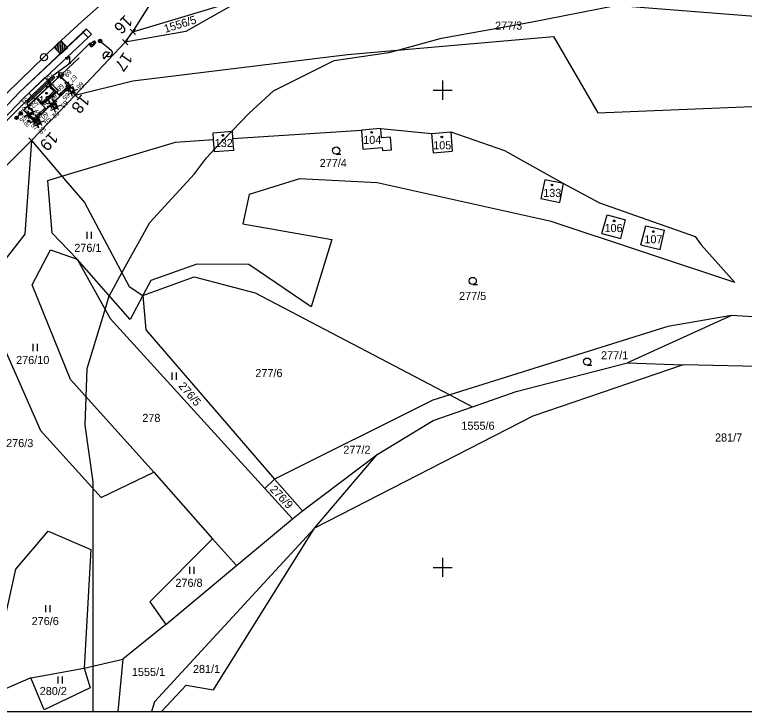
# Model space of a CAD drawing. Extents: x -756640 to -756220, y -1116031 to -1115741.
# Drawn here: x -756489.7 to -756336.8, y -1116030.2 to -1115884.2 of the extents above; entities that cross this region are included whole.
import ezdxf

# ---------------------------------------------------------------- set-up
doc = ezdxf.new("R2010")
doc.units = 0
for name, color, linetype in [('BPEJ', 7, 'Continuous'), ('GD_Demolice', 7, 'Continuous'), ('GD_Nový stav', 7, 'Continuous'), ('GD_Starý stav', 7, 'Continuous'), ('Groma (60)', 7, 'Continuous'), ('Katastr_HRANICE DRÁHY', 7, 'Continuous'), ('Katastr_Hranice parcel', 7, 'Continuous'), ('Katastr_Parcelní čísla', 7, 'Continuous'), ('Katastr_Slučkované čáry', 7, 'Continuous'), ('Katastr_Značky kultur', 7, 'Continuous'), ('Vrstva 7', 7, 'Continuous'), ('čtvercová síť', 7, 'Continuous')]:
    doc.layers.add(name, color=color, linetype=linetype)

# ---------------------------------------------------------------- blocks, each defined once
blk = doc.blocks.new('POINT_DISPLAY')
for p, q in [((-0.56, -0.56), (0.56, 0.56)), ((-0.56, 0.56), (0.56, -0.56))]:
    blk.add_line(p, q)
blk = doc.blocks.new('C691')
at = {"layer": 'čtvercová síť'}
for p, q in [((0, 0.5), (0, -0.5)), ((-0.5, 0), (0.5, 0))]:
    blk.add_line(p, q, dxfattribs=at)

msp = doc.modelspace()

# ---------------------------------------------------------------- linework, layer by layer
at = {"layer": 'BPEJ'}
msp.add_lwpolyline([(-756473.24, -1116030.18), (-756473.24, -1116029.59), (-756473.24, -1116022.8), (-756473.24, -1116020.66), (-756473.24, -1116000), (-756473.24, -1115987.16), (-756473.24, -1115983.5), (-756473.24, -1115982.06), (-756474.94, -1115970.18), (-756474.73, -1115964.28), (-756474.51, -1115958.3), (-756470.74, -1115945.96), (-756469.86, -1115943.07), (-756469.84, -1115943.03), (-756467.21, -1115938.28), (-756461.36, -1115927.75), (-756456.69, -1115922.66), (-756452.02, -1115917.57), (-756449.48, -1115914.17), (-756447.85, -1115912.47), (-756444.19, -1115908.63), (-756440.57, -1115904.84), (-756435.47, -1115900.17), (-756422.74, -1115893.8), (-756411.29, -1115892.11), (-756409.41, -1115891.6), (-756400.26, -1115889.14), (-756381.59, -1115885.74), (-756363.76, -1115882.25)], dxfattribs=at)
at = {"layer": 'Defpoints'}
msp.add_line((-756640.13, -1116030.18), (-756220.13, -1116030.18), dxfattribs=at)
at = {"layer": 'GD_Demolice'}
for p, q in [((-756471.89, -1115889.36), (-756471.83, -1115890.08)), ((-756471.61, -1115889.36), (-756471.55, -1115890.02)), ((-756471.47, -1115889.95), (-756469.46, -1115891.64)), ((-756469.79, -1115892.04), (-756471.05, -1115893.54)), ((-756478.56, -1115899.7), (-756478.39, -1115899.86)), ((-756477.8, -1115900.42), (-756478.56, -1115899.7)), ((-756478.39, -1115899.86), (-756477.91, -1115899.35)), ((-756477.32, -1115899.91), (-756478.05, -1115899.21)), ((-756477.32, -1115899.91), (-756477.91, -1115899.35)), ((-756477.8, -1115900.42), (-756477.32, -1115899.91)), ((-756481.35, -1115903.79), (-756482.11, -1115903.06)), ((-756481.94, -1115903.23), (-756481.46, -1115902.72)), ((-756481.35, -1115903.79), (-756481.94, -1115903.23)), ((-756481.6, -1115902.58), (-756480.87, -1115903.28)), ((-756481.35, -1115903.79), (-756480.87, -1115903.28)), ((-756486.67, -1115904.98), (-756486.52, -1115905.14)), ((-756485.82, -1115904.47), (-756486.52, -1115905.14)), ((-756484.86, -1115907.19), (-756485.62, -1115906.38)), ((-756484.99, -1115906.03), (-756485.47, -1115906.54)), ((-756484.86, -1115907.19), (-756485.47, -1115906.54)), ((-756485.11, -1115905.9), (-756484.38, -1115906.68)), ((-756484.86, -1115907.19), (-756484.38, -1115906.68))]:
    msp.add_line(p, q, dxfattribs=at)
for points in [[(-756482.33, -1115898.93), (-756480.22, -1115897.04), (-756478.24, -1115898.95)], [(-756486.96, -1115903.31), (-756482.33, -1115898.93), (-756480.41, -1115901)], [(-756480.41, -1115901), (-756478.24, -1115898.95), (-756478.02, -1115899.18), (-756485.7, -1115906.45), (-756486.91, -1115905.2), (-756486.67, -1115904.98)], [(-756482.33, -1115898.93), (-756480.41, -1115901), (-756478.24, -1115898.95)], [(-756486.96, -1115903.31), (-756485.82, -1115904.47)]]:
    msp.add_lwpolyline(points, dxfattribs=at)
msp.add_circle((-756471.76, -1115889.71), 0.375, dxfattribs=at)
msp.add_circle((-756471.76, -1115889.71), 0.375, dxfattribs=at)
for centre, start, end in [((-756470.43, -1115892.78), 49.3451, 230.7502), ((-756469.94, -1115892.21), 230.0476, 50.0476)]:
    msp.add_arc(centre, 0.75, start, end, dxfattribs=at)
at = {"layer": 'GD_Nový stav'}
for p, q in [((-756473.06, -1115889.67), (-756473.12, -1115890.51)), ((-756473.12, -1115890.51), (-756473.06, -1115889.67)), ((-756472.67, -1115890.12), (-756473.06, -1115889.67)), ((-756473.12, -1115890.51), (-756473.97, -1115890.45)), ((-756473.97, -1115890.45), (-756473.58, -1115890.9)), ((-756473.97, -1115890.45), (-756473.12, -1115890.51)), ((-756473.58, -1115890.9), (-756473.12, -1115890.51)), ((-756473.12, -1115890.51), (-756472.67, -1115890.12)), ((-756478.34, -1115893.23), (-756479.07, -1115893.23)), ((-756478.07, -1115894.47), (-756478.26, -1115894.28)), ((-756478.01, -1115894.39), (-756478.18, -1115894.22)), ((-756478.14, -1115894.21), (-756478.14, -1115893.23)), ((-756481.01, -1115900.32), (-756483.92, -1115903.07)), ((-756481.01, -1115900.32), (-756481.09, -1115900.24)), ((-756480.18, -1115901.2), (-756480.39, -1115900.98)), ((-756483.92, -1115903.07), (-756484, -1115902.98)), ((-756483.09, -1115903.95), (-756483.3, -1115903.73))]:
    msp.add_line(p, q, dxfattribs=at)
for points in [[(-756473.97, -1115890.45), (-756473.06, -1115889.67), (-756472.67, -1115890.12), (-756473.58, -1115890.9)], [(-756482.26, -1115898.93), (-756476.19, -1115893.2), (-756476.15, -1115893.23), (-756482.22, -1115898.97)], [(-756487.06, -1115902.44), (-756481.46, -1115897.15), (-756481.26, -1115897.37), (-756486.86, -1115902.66)], [(-756486.73, -1115900.6), (-756483.36, -1115897.33), (-756482.07, -1115898.69), (-756485.49, -1115901.92)], [(-756483.99, -1115902.63), (-756481.45, -1115900.23), (-756482.51, -1115899.1), (-756482.33, -1115898.93), (-756481.09, -1115900.24), (-756484, -1115902.98), (-756485.24, -1115901.68), (-756485.05, -1115901.5)], [(-756485.24, -1115901.68), (-756484, -1115902.98), (-756481.09, -1115900.24), (-756482.33, -1115898.93)], [(-756478.98, -1115898.25), (-756478.28, -1115898.99), (-756478.5, -1115899.2), (-756479.2, -1115898.45)], [(-756478.07, -1115899.21), (-756477.32, -1115900.01), (-756477.83, -1115900.49), (-756478.58, -1115899.69)], [(-756481.62, -1115902.56), (-756480.87, -1115903.36), (-756481.38, -1115903.84), (-756482.13, -1115903.04)], [(-756486.48, -1115905.63), (-756485.93, -1115906.22), (-756485.71, -1115906.01), (-756486.26, -1115905.43)], [(-756485.14, -1115905.88), (-756484.38, -1115906.68), (-756484.89, -1115907.16), (-756485.65, -1115906.36)]]:
    msp.add_lwpolyline(points, close=True, dxfattribs=at)
for points in [[(-756510.49, -1115928.5), (-756494.73, -1115910.99), (-756491.19, -1115906.22), (-756486.18, -1115901.19), (-756481.67, -1115896.93), (-756478.14, -1115894.35), (-756473.87, -1115890.1), (-756473.74, -1115890.25)], [(-756476.17, -1115893.21), (-756482.24, -1115898.95)], [(-756484, -1115902.98), (-756481.09, -1115900.24), (-756480.39, -1115900.98), (-756478.28, -1115898.99), (-756478.07, -1115899.21), (-756485.72, -1115906.43), (-756485.93, -1115906.22), (-756483.3, -1115903.73), (-756484, -1115902.98)], [(-756482.55, -1115901.61), (-756482.37, -1115901.79), (-756480.59, -1115900.11), (-756482.69, -1115897.89)], [(-756485.24, -1115901.75), (-756487.82, -1115904.18), (-756487.13, -1115904.91), (-756487.1, -1115904.88), (-756487.75, -1115904.19), (-756485.2, -1115901.78), (-756485.24, -1115901.75)], [(-756487.11, -1115904.89), (-756487.78, -1115904.19), (-756485.22, -1115901.76)], [(-756488.11, -1115904.64), (-756488.18, -1115904.57), (-756489.58, -1115906), (-756489.51, -1115906.07), (-756488.11, -1115904.64)], [(-756488.11, -1115904.64), (-756488.18, -1115904.57), (-756489.58, -1115906), (-756489.51, -1115906.07), (-756488.11, -1115904.64)]]:
    msp.add_lwpolyline(points, dxfattribs=at)
for centre, radius in [((-756478.14, -1115894.35), 0.141), ((-756478.14, -1115894.35), 0.141), ((-756483, -1115900.64), 0.175), ((-756488.41, -1115904.87), 0.35), ((-756489.28, -1115905.77), 0.35), ((-756486.68, -1115906.45), 0.188)]:
    msp.add_circle(centre, radius, dxfattribs=at)
for centre, start, end in [((-756478.42, -1115893.23), 359.9837, 179.9837), ((-756478.7, -1115893.23), 179.2811, 0.6862)]:
    msp.add_arc(centre, 0.281, start, end, dxfattribs=at)
at = {"layer": 'GD_Starý stav'}
for p, q in [((-756471.39, -1115881.91), (-756475.58, -1115885.63)), ((-756475.58, -1115885.63), (-756480.69, -1115890.31)), ((-756475.45, -1115887.95), (-756488.75, -1115900.48)), ((-756488.72, -1115900.49), (-756475.33, -1115887.92)), ((-756474.6, -1115887.22), (-756475.45, -1115887.95)), ((-756475.33, -1115887.92), (-756474.6, -1115887.22)), ((-756475.33, -1115887.92), (-756474.28, -1115888.97)), ((-756480.46, -1115892.07), (-756480.33, -1115890)), ((-756480.1, -1115892.47), (-756479.94, -1115889.65)), ((-756480.69, -1115890.31), (-756491.34, -1115900.62)), ((-756481.16, -1115891.28), (-756481.13, -1115890.7)), ((-756480.81, -1115891.68), (-756480.73, -1115890.35)), ((-756479.71, -1115892.12), (-756479.59, -1115890.04)), ((-756479.31, -1115891.77), (-756479.23, -1115890.44)), ((-756478.91, -1115891.41), (-756478.88, -1115890.84)), ((-756488.75, -1115900.48), (-756500.01, -1115912.23)), ((-756499.99, -1115912.26), (-756488.72, -1115900.49))]:
    msp.add_line(p, q, dxfattribs=at)
msp.add_lwpolyline([(-756518.61, -1115933.55), (-756517.48, -1115934.49), (-756513.05, -1115929.32), (-756507.59, -1115923.05), (-756498.92, -1115913.24), (-756487.78, -1115901.64), (-756474.28, -1115888.97), (-756473.57, -1115888.27), (-756474.6, -1115887.22)], dxfattribs=at)
msp.add_lwpolyline([(-756481.43, -1115890.98), (-756479.94, -1115889.65), (-756478.61, -1115891.14), (-756480.1, -1115892.47)], close=True, dxfattribs=at)
at = {"layer": 'Katastr_HRANICE DRÁHY'}
for points in [[(-756464.9, -1115887.76), (-756458.35, -1115877.27)], [(-756466.5, -1115889.92), (-756464.9, -1115887.76)], [(-756466.5, -1115889.92), (-756476.99, -1115901.06)], [(-756476.99, -1115901.06), (-756486.16, -1115910.54)], [(-756507.58, -1115932.04), (-756486.16, -1115910.54)]]:
    msp.add_lwpolyline(points, dxfattribs=at)
at = {"layer": 'Katastr_Hranice parcel'}
for points in [[(-756323.04, -1115885.48), (-756423.52, -1115877.5)], [(-756464.9, -1115887.76), (-756441.61, -1115880.7)], [(-756441.61, -1115880.7), (-756453.8, -1115887.71)], [(-756453.8, -1115887.71), (-756466.5, -1115889.92)], [(-756419.96, -1115892.51), (-756376.76, -1115888.79)], [(-756376.76, -1115888.79), (-756367.5, -1115904.78)], [(-756464.89, -1115898.03), (-756419.96, -1115892.51)], [(-756482.31, -1115899.02), (-756480.17, -1115896.98)], [(-756478.19, -1115898.99), (-756480.17, -1115896.98)], [(-756482.31, -1115899.02), (-756486.91, -1115903.37)], [(-756477.97, -1115899.22), (-756478.19, -1115898.99)], [(-756476.99, -1115901.06), (-756464.89, -1115898.03)], [(-756481.53, -1115902.57), (-756478.56, -1115899.77)], [(-756478.56, -1115899.77), (-756477.79, -1115900.58)], [(-756477.21, -1115900.02), (-756477.97, -1115899.22)], [(-756477.79, -1115900.58), (-756477.21, -1115900.02)], [(-756486.91, -1115903.37), (-756485.86, -1115904.54)], [(-756485.02, -1115905.88), (-756482.12, -1115903.14)], [(-756482.12, -1115903.14), (-756481.36, -1115903.94)], [(-756480.77, -1115903.38), (-756481.53, -1115902.57)], [(-756481.36, -1115903.94), (-756480.77, -1115903.38)], [(-756367.5, -1115904.78), (-756331.81, -1115903.26)], [(-756486.69, -1115905.05), (-756486.92, -1115905.26)], [(-756486.92, -1115905.26), (-756485.69, -1115906.51)], [(-756486.56, -1115905.19), (-756486.69, -1115905.05)], [(-756485.86, -1115904.54), (-756486.56, -1115905.19)], [(-756485.69, -1115906.51), (-756485.62, -1115906.44)], [(-756485.62, -1115906.44), (-756484.86, -1115907.25)], [(-756484.27, -1115906.69), (-756485.02, -1115905.88)], [(-756484.86, -1115907.25), (-756484.27, -1115906.69)], [(-756444.03, -1115910.1), (-756416.99, -1115908.36)], [(-756412.96, -1115908.04), (-756416.99, -1115908.36)], [(-756416.99, -1115908.36), (-756416.69, -1115912.35)], [(-756412.82, -1115909.99), (-756412.96, -1115908.04)], [(-756412.96, -1115908.04), (-756402.35, -1115909.07)], [(-756448.12, -1115908.94), (-756444.14, -1115908.63)], [(-756448.01, -1115910.36), (-756448.12, -1115908.94)], [(-756444.14, -1115908.63), (-756444.03, -1115910.1)], [(-756410.94, -1115909.83), (-756412.82, -1115909.99)], [(-756410.74, -1115912.51), (-756410.94, -1115909.83)], [(-756402.35, -1115909.07), (-756398.28, -1115908.76)], [(-756402.35, -1115909.07), (-756402.01, -1115913.15)], [(-756398.28, -1115908.76), (-756397.98, -1115912.81)], [(-756398.28, -1115908.76), (-756387.02, -1115912.62)], [(-756486.16, -1115910.54), (-756487.59, -1115930.19)], [(-756486.16, -1115910.54), (-756479.77, -1115918.03)], [(-756479.77, -1115918.03), (-756456, -1115910.87)], [(-756456, -1115910.87), (-756448.01, -1115910.36)], [(-756447.82, -1115912.93), (-756448.01, -1115910.36)], [(-756444.03, -1115910.1), (-756443.83, -1115912.62)], [(-756443.83, -1115912.62), (-756447.82, -1115912.93)], [(-756416.69, -1115912.35), (-756412.67, -1115912.05)], [(-756412.67, -1115912.05), (-756412.63, -1115912.66)], [(-756412.63, -1115912.66), (-756410.74, -1115912.51)], [(-756402.01, -1115913.15), (-756397.98, -1115912.81)], [(-756387.02, -1115912.62), (-756374.65, -1115919.58)], [(-756482.71, -1115918.91), (-756479.77, -1115918.03)], [(-756481.84, -1115930), (-756482.71, -1115918.91)], [(-756479.77, -1115918.03), (-756475.05, -1115923.56)], [(-756429.99, -1115918.55), (-756440.52, -1115921.89)], [(-756413.71, -1115919.42), (-756429.99, -1115918.55)], [(-756378.59, -1115918.76), (-756379.44, -1115922.71)], [(-756374.65, -1115919.58), (-756378.59, -1115918.76)], [(-756377.28, -1115927.53), (-756413.71, -1115919.42)], [(-756375.47, -1115923.53), (-756374.65, -1115919.58)], [(-756374.65, -1115919.58), (-756367.13, -1115923.64)], [(-756440.52, -1115921.89), (-756441.89, -1115927.98)], [(-756475.05, -1115923.56), (-756465.67, -1115941.16)], [(-756379.44, -1115922.71), (-756375.47, -1115923.53)], [(-756367.13, -1115923.64), (-756347.06, -1115930.66)], [(-756366.62, -1115930.04), (-756365.53, -1115926.13)], [(-756365.53, -1115926.13), (-756361.66, -1115927.15)], [(-756441.89, -1115927.98), (-756423.19, -1115931.32)], [(-756338.77, -1115940.31), (-756377.28, -1115927.53)], [(-756362.69, -1115931.08), (-756361.66, -1115927.15)], [(-756358.46, -1115932.44), (-756357.42, -1115928.46)], [(-756357.42, -1115928.46), (-756353.53, -1115929.37)], [(-756354.43, -1115933.4), (-756353.53, -1115929.37)], [(-756487.59, -1115930.19), (-756494.5, -1115938.97)], [(-756476.59, -1115935.4), (-756481.84, -1115930)], [(-756423.19, -1115931.32), (-756427.52, -1115945.41)], [(-756366.62, -1115930.04), (-756362.69, -1115931.08)], [(-756347.06, -1115930.66), (-756345.79, -1115932.44)], [(-756358.46, -1115932.44), (-756354.43, -1115933.4)], [(-756345.79, -1115932.44), (-756338.77, -1115940.31)], [(-756486.05, -1115940.81), (-756482.17, -1115933.46)], [(-756482.17, -1115933.46), (-756476.59, -1115935.4)], [(-756476.59, -1115935.4), (-756469.68, -1115947.87)], [(-756465.5, -1115948.04), (-756476.59, -1115935.4)], [(-756451.52, -1115936.47), (-756461.17, -1115939.92)], [(-756440.58, -1115936.52), (-756451.52, -1115936.47)], [(-756427.52, -1115945.41), (-756440.58, -1115936.52)], [(-756462.85, -1115943.03), (-756452.04, -1115939.11)], [(-756461.17, -1115939.92), (-756462.85, -1115943.03)], [(-756452.04, -1115939.11), (-756439.28, -1115942.48)], [(-756477.98, -1115960.65), (-756486.05, -1115940.81)], [(-756465.67, -1115941.16), (-756462.85, -1115943.03)], [(-756462.85, -1115943.03), (-756465.5, -1115948.04)], [(-756462.85, -1115943.03), (-756462.21, -1115950.25)], [(-756439.28, -1115942.48), (-756398.47, -1115963.87)], [(-756469.68, -1115947.87), (-756437.29, -1115983.49)], [(-756339.47, -1115947.22), (-756361.23, -1115957.17)], [(-756339.47, -1115947.22), (-756352.82, -1115949.54)], [(-756308.41, -1115949.21), (-756339.47, -1115947.22)], [(-756494.55, -1115948.16), (-756484.25, -1115971.34)], [(-756352.82, -1115949.54), (-756398.47, -1115963.87)], [(-756462.21, -1115950.25), (-756435.24, -1115981.54)], [(-756384.62, -1115963.18), (-756361.23, -1115957.17)], [(-756361.23, -1115957.17), (-756349.57, -1115957.55)], [(-756349.57, -1115957.55), (-756381.08, -1115968.31)], [(-756308.96, -1115958.44), (-756349.57, -1115957.55)], [(-756460.55, -1115980.07), (-756477.98, -1115960.65)], [(-756393.75, -1115966.34), (-756384.62, -1115963.18)], [(-756398.47, -1115963.87), (-756402.04, -1115964.99)], [(-756398.47, -1115963.87), (-756393.75, -1115966.34)], [(-756402.04, -1115964.99), (-756435.24, -1115981.54)], [(-756402, -1115969.19), (-756393.75, -1115966.34)], [(-756381.08, -1115968.31), (-756426.83, -1115991.78)], [(-756413.71, -1115976.37), (-756402, -1115969.19)], [(-756484.25, -1115971.34), (-756471.53, -1115985.39)], [(-756429.38, -1115988.18), (-756413.71, -1115976.37)], [(-756426.83, -1115991.78), (-756413.71, -1115976.37)], [(-756471.53, -1115985.39), (-756460.55, -1115980.07)], [(-756460.55, -1115980.07), (-756448.2, -1115994)], [(-756435.24, -1115981.54), (-756437.29, -1115983.49)], [(-756435.24, -1115981.54), (-756429.38, -1115988.18)], [(-756437.29, -1115983.49), (-756431.48, -1115989.84)], [(-756431.48, -1115989.84), (-756429.38, -1115988.18)], [(-756443.21, -1115999.63), (-756431.48, -1115989.84)], [(-756489.43, -1116000.35), (-756482.69, -1115992.4)], [(-756482.69, -1115992.4), (-756473.69, -1115996.24)], [(-756426.83, -1115991.78), (-756460.41, -1116028.2)], [(-756448.04, -1116025.64), (-756426.83, -1115991.78)], [(-756448.2, -1115994), (-756461.34, -1116007.19)], [(-756448.2, -1115994), (-756443.21, -1115999.63)], [(-756473.69, -1115996.24), (-756475.12, -1116021.09)], [(-756457.99, -1116011.97), (-756443.21, -1115999.63)], [(-756495.36, -1116027.02), (-756489.43, -1116000.35)], [(-756461.34, -1116007.19), (-756457.99, -1116011.97)], [(-756457.99, -1116011.97), (-756467.05, -1116019.26)], [(-756475.12, -1116021.09), (-756467.05, -1116019.26)], [(-756467.05, -1116019.26), (-756468.1, -1116030.18)], [(-756486.31, -1116023.12), (-756475.12, -1116021.09)], [(-756475.12, -1116021.09), (-756473.86, -1116025.26)], [(-756486.31, -1116023.12), (-756495.36, -1116027.02)], [(-756483.51, -1116029.87), (-756486.31, -1116023.12)], [(-756473.86, -1116025.26), (-756483.51, -1116029.87)], [(-756458.93, -1116030.18), (-756453.74, -1116024.65)], [(-756453.74, -1116024.65), (-756448.04, -1116025.64)], [(-756460.41, -1116028.2), (-756460.99, -1116030.18)]]:
    msp.add_lwpolyline(points, dxfattribs=at)
at = {"layer": 'Katastr_Slučkované čáry'}
for points in [[(-756480.35, -1115901.06), (-756482.31, -1115899.02)], [(-756478.19, -1115898.99), (-756480.35, -1115901.06)]]:
    msp.add_lwpolyline(points, dxfattribs=at)
at = {"layer": 'Katastr_Značky kultur'}
for p, q in [((-756422.31, -1115913.41), (-756421.31, -1115913.41)), ((-756474.58, -1115929.69), (-756474.58, -1115931.19)), ((-756473.58, -1115931.19), (-756473.58, -1115929.69)), ((-756393.7, -1115940.73), (-756392.7, -1115940.73)), ((-756485.88, -1115953.19), (-756485.88, -1115954.69)), ((-756484.88, -1115954.69), (-756484.88, -1115953.19)), ((-756369.71, -1115957.63), (-756368.71, -1115957.63)), ((-756456.78, -1115959.17), (-756456.78, -1115960.67)), ((-756455.78, -1115960.67), (-756455.78, -1115959.17)), ((-756453.07, -1115999.88), (-756453.07, -1116001.38)), ((-756452.07, -1116001.38), (-756452.07, -1115999.88)), ((-756483.24, -1116007.89), (-756483.24, -1116009.39)), ((-756482.24, -1116009.39), (-756482.24, -1116007.89)), ((-756480.65, -1116022.84), (-756480.65, -1116024.34)), ((-756479.65, -1116024.34), (-756479.65, -1116022.84))]:
    msp.add_line(p, q, dxfattribs=at)
for centre, radius in [((-756446.08, -1115909.49), 0.175), ((-756414.86, -1115908.85), 0.175), ((-756400.18, -1115909.81), 0.175), ((-756422.31, -1115912.66), 0.75), ((-756377.09, -1115919.86), 0.175), ((-756364.05, -1115927.4), 0.175), ((-756355.85, -1115929.63), 0.175), ((-756393.7, -1115939.98), 0.75), ((-756369.71, -1115956.88), 0.75)]:
    msp.add_circle(centre, radius, dxfattribs=at)
at = {"layer": 'Vrstva 7'}
msp.add_line((-756479.93, -1115896.77), (-756480, -1115896.83), dxfattribs=at)
for centre, radius in [((-756483.54, -1115893.08), 0.75), ((-756479.96, -1115896.8), 0.5)]:
    msp.add_circle(centre, radius, dxfattribs=at)

# ---------------------------------------------------------------- block references
at = {"layer": 'Groma (60)'}
for p, rotation in [((-756464.9, -1115887.76), 180), ((-756466.5, -1115889.92), 180), ((-756480.17, -1115896.98), 63.74607776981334), ((-756482.31, -1115899.02), 63.74607776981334), ((-756478.56, -1115899.77), 63.74607776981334), ((-756478.19, -1115898.99), 63.74607776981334), ((-756477.79, -1115900.58), 63.74607776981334), ((-756477.21, -1115900.02), 63.74607776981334), ((-756476.99, -1115901.06), 180), ((-756481.53, -1115902.57), 63.74607776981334), ((-756486.91, -1115903.37), 63.74607776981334), ((-756485.86, -1115904.54), 63.74607776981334), ((-756482.12, -1115903.14), 63.74607776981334), ((-756481.36, -1115903.94), 63.74607776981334), ((-756480.77, -1115903.38), 63.74607776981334), ((-756486.92, -1115905.26), 63.74607776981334), ((-756486.69, -1115905.05), 63.74607776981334), ((-756486.56, -1115905.19), 63.74607776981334), ((-756485.02, -1115905.88), 63.74607776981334), ((-756485.69, -1115906.51), 63.74607776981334), ((-756485.62, -1115906.44), 63.74607776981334), ((-756484.86, -1115907.25), 63.74607776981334), ((-756484.27, -1115906.69), 63.74607776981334), ((-756486.16, -1115910.54), 180)]:
    msp.add_blockref('POINT_DISPLAY', p, dxfattribs=dict(at, rotation=rotation))
at = {"layer": 'čtvercová síť', "xscale": 4, "yscale": 4}
for p in [(-756400, -1115900), (-756400, -1116000)]:
    msp.add_blockref('C691', p, dxfattribs=at)

# ---------------------------------------------------------------- texts
at = {"layer": 'Groma (60)'}
for s, height, rotation, p in [('16', 2.5, 225.7849, (-756466.49, -1115884.05)), ('17', 2.5, 234.6048, (-756466.76, -1115891.85)), ('69', 1, 228.6932, (-756478.38, -1115895.59)), ('70', 1, 222.7278, (-756481.99, -1115896.3)), ('67', 1, 226.0445, (-756477.2, -1115896.65)), ('68', 1, 222.1382, (-756479.91, -1115898.56)), ('66', 1, 224.5185, (-756475.79, -1115898.15)), ('64', 1, 216.8847, (-756481.31, -1115900.58)), ('65', 1, 224.0313, (-756478.7, -1115900.49)), ('51', 1, 220.8795, (-756487.21, -1115901.45)), ('52', 1, 218.8999, (-756485.22, -1115902.1)), ('61', 1, 217.0315, (-756482.95, -1115901.69)), ('63', 1, 228.305, (-756479.12, -1115902.08)), ('18', 2.5, 230.3376, (-756475.61, -1115900.7)), ('54', 1, 225.6383, (-756487.79, -1115903.45)), ('55', 1, 226.5788, (-756487.74, -1115905.1)), ('53', 1, 220.8492, (-756484.76, -1115904.04)), ('60', 1, 223.9597, (-756483.26, -1115904.37)), ('62', 1, 221.4452, (-756480.85, -1115904.29)), ('56', 1, 226.2726, (-756486.8, -1115906.02)), ('57', 1, 314.1235, (-756486.4, -1115907.43)), ('59', 1, 227.6619, (-756482.73, -1115905.38)), ('58', 1, 225.5007, (-756483.76, -1115907.52)), ('19', 2.5, 226.2584, (-756482.09, -1115908.56))]:
    msp.add_text(s, height=height, rotation=rotation, dxfattribs=at).set_placement(p)
at = {"layer": 'Katastr_Parcelní čísla'}
for s, rotation, p in [('1556/5', 17.1589, (-756458.1, -1115888)), ('276/5', 310.6226, (-756455.45, -1115962.07)), ('276/9', 313.8527, (-756436.33, -1115983.78))]:
    msp.add_text(s, height=1.7, rotation=rotation, dxfattribs=at).set_placement(p)
for s, p in [('277/3', (-756389.01, -1115887.33)), ('131', (-756484.64, -1115902.94)), ('104', (-756416.65, -1115911.27)), ('132', (-756447.77, -1115911.92)), ('105', (-756401.98, -1115912.41)), ('277/4', (-756425.77, -1115916.11)), ('133', (-756378.93, -1115922.38)), ('106', (-756366.08, -1115929.74)), ('107', (-756357.72, -1115932.1)), ('276/1', (-756477.19, -1115933.89)), ('277/5', (-756396.56, -1115943.98)), ('276/10', (-756489.38, -1115957.39)), ('277/1', (-756366.8, -1115956.41)), ('277/6', (-756439.25, -1115960.13)), ('278', (-756462.94, -1115969.53)), ('1555/6', (-756396.07, -1115971.16)), ('281/7', (-756342.92, -1115973.64)), ('276/3', (-756491.47, -1115974.8)), ('277/2', (-756420.81, -1115976.2)), ('276/8', (-756456, -1116004.08)), ('276/6', (-756486.13, -1116012.09)), ('1555/1', (-756465.12, -1116022.76)), ('281/1', (-756452.33, -1116022.13)), ('280/2', (-756484.43, -1116026.76))]:
    msp.add_text(s, height=1.7, dxfattribs=at).set_placement(p)

doc.saveas('drawing.dxf')
